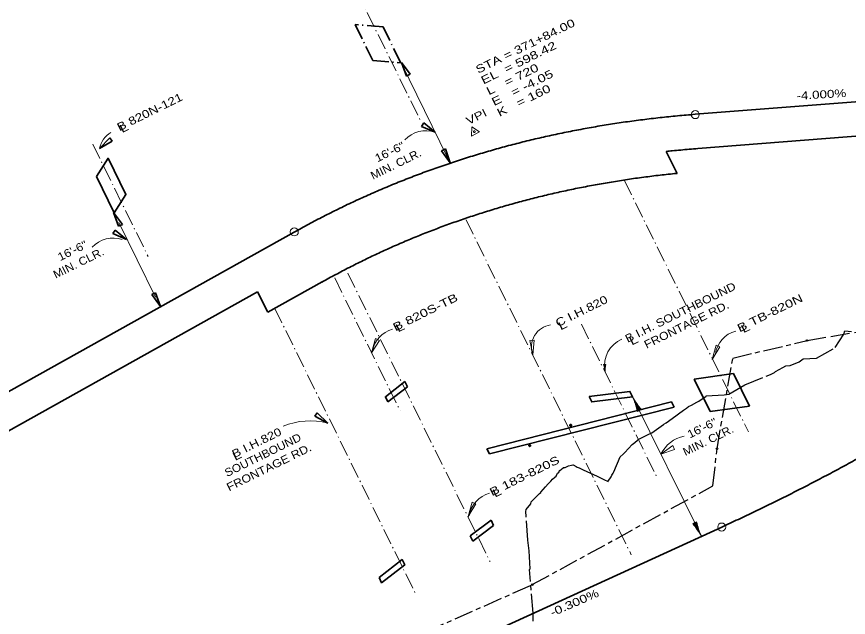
# Model space of a CAD drawing. Extents: x 2356431 to 2371438, y 6972864 to 6982525.
# Drawn here: x 2364327 to 2365783, y 6976877 to 6977927 of the extents above; entities that cross this region are included whole.
import ezdxf
from ezdxf.enums import TextEntityAlignment as Align

# ---------------------------------------------------------------- set-up
doc = ezdxf.new("R2010")
doc.units = 0
doc.header["$LTSCALE"] = 5.6
doc.header["$PDMODE"] = 32
doc.header["$PDSIZE"] = 2.8
for name, pattern in [('DASH_DOUBLE_DOT', [9.2, 5, -1.2, 0.3, -1.2, 0.3, -1.2]), ('DOT_DASHED', [7.7, 5, -1.2, 0.3, -1.2]), ('LONG_DASH_SHORT_DASH', [9.9, 6, -1.2, 1.5, -1.2]), ('LONG_DASHED', [7.5, 6, -1.5])]:
    doc.linetypes.add(name, pattern=pattern)
for name, color, linetype, lineweight in [('1', 7, 'Continuous', 25), ('2', 7, 'Continuous', 35), ('4', 7, 'LONG_DASHED', 35), ('44', 7, 'Continuous', 13), ('52', 7, 'Continuous', 25), ('53', 7, 'Continuous', 13), ('55', 7, 'Continuous', 13), ('61', 7, 'Continuous', 13)]:
    doc.layers.add(name, color=color, linetype=linetype, lineweight=lineweight)

msp = doc.modelspace()

# ---------------------------------------------------------------- linework, layer by layer
at = {"layer": '1', "lineweight": 13}
for p, q in [((2365000.648, 6977844.926), (2365081.574, 6977680.954)), ((2364506.093, 6977566.991), (2364570.478, 6977436.533)), ((2365525.628, 6977018.423), (2365405.321, 6977262.187)), ((2365417.237, 6977238.348), (2365406.115, 6977260.882)), ((2365416.34, 6977237.905), (2365408.719, 6977253.347)), ((2365415.443, 6977237.464), (2365411.139, 6977246.182)), ((2365418.134, 6977238.79), (2365411.627, 6977251.972)), ((2365414.546, 6977237.02), (2365412.438, 6977241.292)), ((2365419.03, 6977239.233), (2365415.245, 6977246.903)), ((2365419.927, 6977239.677), (2365418.525, 6977242.519)), ((2365420.555, 6977239.987), (2365413.686, 6977236.595)), ((2365517.272, 6977044.018), (2365510.402, 6977040.629)), ((2365511.262, 6977041.053), (2365513.371, 6977036.781)), ((2365512.16, 6977041.495), (2365516.462, 6977032.776)), ((2365513.056, 6977041.939), (2365520.677, 6977026.497)), ((2365513.953, 6977042.381), (2365525.074, 6977019.846)), ((2365514.85, 6977042.824), (2365521.355, 6977029.641)), ((2365515.746, 6977043.266), (2365519.532, 6977035.596)), ((2365516.644, 6977043.708), (2365518.047, 6977040.866))]:
    msp.add_line(p, q, dxfattribs=at)
at = {"layer": '1', "linetype": 'LONG_DASHED'}
msp.add_line((2365710.484, 6977360.825), (2365813.438, 6977378.181), dxfattribs=at)
at = {"layer": '1', "linetype": 'LONG_DASH_SHORT_DASH'}
msp.add_line((2365580.625, 6977330.192), (2365710.484, 6977360.825), dxfattribs=at)
at = {"layer": '1', "lineweight": 35}
for p, q in [((2365581.757, 6977302.943), (2365512.819, 6977293.496)), ((2365581.757, 6977302.943), (2365609.754, 6977246.215)), ((2365011.429, 6977279.861), (2365006.852, 6977288.965)), ((2365512.819, 6977293.496), (2365540.817, 6977236.768)), ((2365011.429, 6977279.861), (2364977.202, 6977253.322)), ((2365150.172, 6977171.65), (2365473.244, 6977253.649)), ((2365154.697, 6977162.482), (2365477.769, 6977244.48)), ((2365540.817, 6977236.768), (2365609.754, 6977246.215)), ((2365121.151, 6977019.338), (2365157.582, 6977046.748)), ((2365162.086, 6977037.624), (2365125.655, 6977010.212))]:
    msp.add_line(p, q, dxfattribs=at)
at = {"layer": '1', "linetype": 'DOT_DASHED', "lineweight": 35}
for p, q in [((2365473.244, 6977253.649), (2365477.769, 6977244.48)), ((2365150.172, 6977171.65), (2365154.697, 6977162.482)), ((2365162.086, 6977037.624), (2365157.582, 6977046.748)), ((2365125.655, 6977010.212), (2365121.151, 6977019.338))]:
    msp.add_line(p, q, dxfattribs=at)
msp.add_lwpolyline([(2364919.576, 6977913.6), (2364950.571, 6977850.73), (2364999.475, 6977846.547), (2364968.548, 6977909.412)], close=True, dxfattribs=at)
at = {"layer": '1', "lineweight": 35}
for points in [[(2364467.401, 6977647.828), (2364487.385, 6977679.495), (2364518.522, 6977616.406), (2364498.108, 6977584.057)], [(2365329.052, 6977263.07), (2365333.744, 6977253.562), (2365405.321, 6977262.187), (2365400.629, 6977271.695)], [(2364961.741, 6976946.434), (2364966.132, 6976937.183), (2365006.446, 6976968.48), (2365001.96, 6976977.658)]]:
    msp.add_lwpolyline(points, close=True, dxfattribs=at)
at = {"layer": '1', "linetype": 'LONG_DASH_SHORT_DASH'}
for points in [[(2365696.943, 6977323.601), (2365703.747, 6977328.612), (2365727.251, 6977329.851), (2365759.535, 6977348.332), (2365774.896, 6977372.139), (2365776.602, 6977378.009), (2365788.527, 6977376.384)], [(2365545.923, 6977106.752), (2365552.968, 6977171.566), (2365580.625, 6977330.192)], [(2365231.489, 6976870.234), (2365231.213, 6976884.244), (2365224.719, 6976960.192), (2365225.915, 6976961.587), (2365224.366, 6976993.249), (2365222.187, 6977011.741), (2365218.96, 6977053.431), (2365218.152, 6977061.273), (2365218.287, 6977061.925), (2365218.398, 6977062.063), (2365219.066, 6977065.585), (2365226.967, 6977075.214), (2365227.979, 6977078.764), (2365234.24, 6977085.146), (2365241.389, 6977092.19), (2365242.571, 6977093.319), (2365244.909, 6977095.133), (2365244.9, 6977095.738), (2365252.783, 6977104.706), (2365257.27, 6977110.433), (2365261.913, 6977115.144), (2365264.991, 6977118.395), (2365269.221, 6977121.978), (2365271.718, 6977123.81), (2365273.849, 6977128.888), (2365276.627, 6977130.399), (2365276.375, 6977131.224), (2365278.129, 6977133.77), (2365283.55, 6977138.013), (2365284.587, 6977138.827), (2365287.091, 6977138.567), (2365292.866, 6977141.552), (2365298.467, 6977142.926), (2365300.844, 6977143.241), (2365300.976, 6977143.333), (2365306.357, 6977140.526), (2365307.969, 6977139.499), (2365311.796, 6977138.278), (2365318.665, 6977134.921), (2365343.499, 6977123.765), (2365355.118, 6977117.748), (2365362.208, 6977114.101), (2365362.487, 6977114.484), (2365362.567, 6977114.638), (2365367.769, 6977122.484), (2365369.117, 6977125.399), (2365371.155, 6977128.7), (2365372.591, 6977131.009), (2365383.678, 6977157.619), (2365388.875, 6977161.955), (2365391.856, 6977164.839), (2365404.373, 6977178.738), (2365409.097, 6977182.337), (2365413.963, 6977186.598), (2365414.508, 6977187.142), (2365415.668, 6977187.796), (2365416.15, 6977188.312), (2365432.613, 6977196.484), (2365438.629, 6977199.66), (2365459.612, 6977214.011), (2365459.649, 6977214.049), (2365459.852, 6977214.203), (2365460.088, 6977214.357), (2365463.719, 6977217.099), (2365474.732, 6977224.315), (2365494.511, 6977238.756), (2365499.494, 6977242.419), (2365502.225, 6977244.995), (2365503.001, 6977245.592), (2365508.445, 6977247.6), (2365517.367, 6977252.816), (2365521.103, 6977254.759), (2365533.841, 6977263.766), (2365534.276, 6977264.081), (2365565.437, 6977265.74), (2365573.454, 6977266.921), (2365601.618, 6977283.534), (2365646.577, 6977301.307), (2365653.655, 6977304.84), (2365655.413, 6977306.698), (2365668.032, 6977313.69), (2365673.224, 6977316.275), (2365680.834, 6977316.833), (2365696.943, 6977323.601)], [(2364790.419, 6976739.461), (2365229.723, 6976933.969), (2365545.923, 6977106.752)]]:
    msp.add_lwpolyline(points, dxfattribs=at)
at = {"layer": '1', "lineweight": 35}
msp.add_lwpolyline([(2364977.202, 6977253.322), (2364972.624, 6977262.427), (2365006.852, 6977288.965)], dxfattribs=at)
at = {"layer": '1', "lineweight": 13}
for centre, radius, start, end in [((2364513.594, 6977688.517), 41.969, 120.5749, 168.88863), ((2365043.299, 6977678.665), 49.058, 70.65037, 138.00729), ((2364495.951, 6977490.94), 49.058, 70.65037, 138.00729), ((2365267.375, 6977349.263), 39.159, 98.08545, 200.23887), ((2364998.289, 6977333.312), 49.143, 105.45269, 171.47396), ((2365598.754, 6977330.069), 49.143, 105.45269, 171.47396), ((2365405.905, 6977317.453), 49.6, 113.0172, 190.70759), ((2365272.809, 6977204.748), 144.431, 12.73827, 23.42432), ((2365531.523, 6977332.432), 144.431, 209.11143, 219.79748), ((2364841.191, 6977096.522), 123.831, 75.743, 112.40222), ((2365506.777, 6977136.854), 57.828, 100.98701, 154.21632), ((2365168.069, 6977046.691), 49.143, 105.45269, 171.47396), ((2365399.433, 6976948.181), 144.431, 29.11144, 39.79749), ((2365658.147, 6977075.865), 144.431, 192.73827, 203.42432)]:
    msp.add_arc(centre, radius, start, end, dxfattribs=at)
at = {"layer": '2'}
msp.add_line((2364945.745, 6976753.555), (2365561.252, 6977034.695), dxfattribs=at)
msp.add_spline([(2365561.252, 6977034.695), (2365575.796, 6977041.379), (2365590.308, 6977048.127), (2365604.788, 6977054.941), (2365619.235, 6977061.819), (2365633.651, 6977068.763), (2365648.034, 6977075.771), (2365662.386, 6977082.845), (2365676.705, 6977089.985), (2365690.992, 6977097.189), (2365705.247, 6977104.458), (2365719.47, 6977111.792), (2365733.66, 6977119.192), (2365747.819, 6977126.656), (2365761.945, 6977134.186), (2365776.039, 6977141.781), (2365790.101, 6977149.44), (2365804.131, 6977157.166), (2365818.129, 6977164.956), (2365832.095, 6977172.812), (2365846.028, 6977180.732), (2365859.93, 6977188.717), (2365873.799, 6977196.768), (2365887.636, 6977204.883), (2365901.441, 6977213.065), (2365915.214, 6977221.311), (2365928.954, 6977229.622), (2365942.663, 6977237.998), (2365944.224, 6977238.957)], degree=3, dxfattribs=at)
at = {"layer": '4'}
for p in [(2365296.922, 6977212.479), (2365225.179, 6977177.071)]:
    msp.add_point(p, dxfattribs=at)
at = {"layer": '44', "linetype": 'DOT_DASHED'}
for p, q in [((2364902.524, 6978011.936), (2365035.302, 6977742.903)), ((2364460.541, 6977704.253), (2364557.611, 6977507.57)), ((2365391.104, 6977640.512), (2365607.921, 6977201.195)), ((2365113.876, 6977571.911), (2365403.022, 6976986.041)), ((2364906.988, 6977478.376), (2365155.757, 6976974.317)), ((2364883.932, 6977470.142), (2364998.439, 6977238.127)), ((2364779.185, 6977416.983), (2365026.664, 6976915.539)), ((2365315.906, 6977389.129), (2365448.682, 6977120.097))]:
    msp.add_line(p, q, dxfattribs=at)
at = {"layer": '52', "linetype": 'LONG_DASH_SHORT_DASH', "lineweight": 13}
for p, q in [((2365124.111, 6977734.339), (2365123.13, 6977718.212)), ((2365123.13, 6977718.212), (2365137.59, 6977725.431)), ((2365124.111, 6977734.339), (2365137.59, 6977725.431))]:
    msp.add_line(p, q, dxfattribs=at)
at = {"layer": '52', "lineweight": 13}
for centre in [(2365514.983, 6977755.734), (2364813.317, 6977550.749)]:
    msp.add_circle(centre, 7, dxfattribs=at)
at = {"layer": '52', "linetype": 'LONG_DASH_SHORT_DASH', "lineweight": 13}
msp.add_circle((2365128.269, 6977725.986), 1.5, dxfattribs=at)
at = {"layer": '52'}
for p in [(2365710.484, 6977360.825), (2365552.968, 6977171.566), (2365229.723, 6976933.969)]:
    msp.add_point(p, dxfattribs=at)
at = {"layer": '53', "lineweight": 35}
for p, q in [((2365514.614, 6977756.311), (2366355.88, 6977822.203)), ((2365519.299, 6977696.494), (2366384.586, 6977764.268)), ((2365464.089, 6977691.365), (2365482.971, 6977653.107)), ((2362763.128, 6976407.438), (2364813.246, 6977550.503)), ((2364766.838, 6977410.135), (2364861.944, 6977463.162)), ((2362792.347, 6976355.033), (2364749.113, 6977446.049)), ((2364749.113, 6977446.049), (2364766.838, 6977410.135))]:
    msp.add_line(p, q, dxfattribs=at)
at = {"layer": '53', "linetype": 'DASH_DOUBLE_DOT', "lineweight": 35}
for points in [[(2365009.623, 6977823.052), (2365000.902, 6977847.113), (2365016.306, 6977826.411)], [(2365039.972, 6977741.424), (2365059.553, 6977724.953), (2365035.859, 6977735.178)], [(2364494.727, 6977709.123), (2364472.41, 6977696.605), (2364490.331, 6977715.173)], [(2365077.784, 6977695.824), (2365086.084, 6977671.621), (2365071.041, 6977692.589)], [(2364505.819, 6977560.515), (2364497.098, 6977584.576), (2364512.502, 6977563.874)], [(2364500.082, 6977554.041), (2364519.663, 6977537.57), (2364495.969, 6977547.795)], [(2364570.611, 6977444.266), (2364578.911, 6977420.063), (2364563.868, 6977441.031)], [(2364853.545, 6977234.584), (2364871.686, 6977216.539), (2364848.927, 6977228.702)]]:
    msp.add_lwpolyline(points, close=True, dxfattribs=at)
at = {"layer": '53'}
msp.add_lwpolyline([(2365478.839, 6977170.513), (2365454.706, 6977162.008), (2365475.545, 6977177.228)], close=True, dxfattribs=at)
at = {"layer": '53', "lineweight": 35}
for points in [[(2364813.246, 6977550.503), (2364825.867, 6977557.466), (2364838.546, 6977564.313), (2364851.282, 6977571.044), (2364864.076, 6977577.658), (2364876.927, 6977584.157), (2364889.836, 6977590.539), (2364902.801, 6977596.805), (2364915.824, 6977602.955), (2364928.905, 6977608.988), (2364942.043, 6977614.905), (2364955.239, 6977620.706), (2364968.491, 6977626.392), (2364981.801, 6977631.96), (2364995.169, 6977637.412), (2365008.594, 6977642.749), (2365022.076, 6977647.969), (2365035.616, 6977653.073), (2365049.213, 6977658.061), (2365062.867, 6977662.932), (2365076.579, 6977667.687), (2365090.348, 6977672.326), (2365104.175, 6977676.85), (2365118.058, 6977681.256), (2365132, 6977685.546), (2365145.999, 6977689.721), (2365160.054, 6977693.778), (2365174.167, 6977697.721), (2365188.338, 6977701.546), (2365202.566, 6977705.255), (2365216.852, 6977708.849), (2365231.195, 6977712.326), (2365245.595, 6977715.687), (2365260.053, 6977718.931), (2365274.568, 6977722.059), (2365289.141, 6977725.072), (2365303.771, 6977727.968), (2365318.458, 6977730.748), (2365333.202, 6977733.411), (2365348.005, 6977735.958), (2365362.864, 6977738.39), (2365377.781, 6977740.705), (2365392.755, 6977742.904), (2365407.786, 6977744.986), (2365422.875, 6977746.952), (2365438.022, 6977748.803), (2365453.225, 6977750.537), (2365468.486, 6977752.155), (2365483.805, 6977753.656), (2365499.18, 6977755.042), (2365514.614, 6977756.311)], [(2365464.089, 6977691.365), (2365474.574, 6977692.464), (2365489.425, 6977693.919), (2365504.331, 6977695.263), (2365519.529, 6977696.512)], [(2364861.55, 6977462.943), (2364873.78, 6977469.69), (2364885.668, 6977476.111), (2364897.607, 6977482.42), (2364909.602, 6977488.621), (2364921.651, 6977494.714), (2364933.753, 6977500.697), (2364945.909, 6977506.572), (2364958.117, 6977512.337), (2364970.381, 6977517.994), (2364982.7, 6977523.542), (2364995.074, 6977528.982), (2365007.503, 6977534.314), (2365019.983, 6977539.535), (2365032.522, 6977544.65), (2365045.117, 6977549.656), (2365057.767, 6977554.554), (2365070.473, 6977559.344), (2365083.232, 6977564.024), (2365096.051, 6977568.597), (2365108.927, 6977573.063), (2365121.859, 6977577.42), (2365134.848, 6977581.669), (2365147.891, 6977585.809), (2365160.995, 6977589.841), (2365174.155, 6977593.766), (2365187.373, 6977597.581), (2365200.651, 6977601.29), (2365213.983, 6977604.889), (2365227.377, 6977608.381), (2365240.829, 6977611.765), (2365254.34, 6977615.04), (2365267.909, 6977618.207), (2365281.535, 6977621.265), (2365295.224, 6977624.215), (2365308.971, 6977627.057), (2365322.779, 6977629.79), (2365336.646, 6977632.415), (2365350.57, 6977634.93), (2365364.558, 6977637.337), (2365378.605, 6977639.636), (2365392.714, 6977641.825), (2365406.882, 6977643.906), (2365421.108, 6977645.877), (2365435.399, 6977647.739), (2365449.753, 6977649.492), (2365464.162, 6977651.137), (2365478.633, 6977652.67), (2365482.971, 6977653.107)]]:
    msp.add_spline(points, degree=3, dxfattribs=at)
at = {"layer": '55'}
for p, q in [((2365354.355, 6977318.718), (2365358.175, 6977319.014)), ((2365354.703, 6977318.823), (2365354.825, 6977317.244)), ((2365355.202, 6977318.863), (2365355.531, 6977314.599)), ((2365355.701, 6977318.901), (2365356.265, 6977311.573)), ((2365356.199, 6977318.94), (2365357.166, 6977306.411)), ((2365356.698, 6977318.978), (2365357.36, 6977310.394)), ((2365357.197, 6977319.017), (2365357.57, 6977314.169)), ((2365357.695, 6977319.055), (2365357.878, 6977316.68))]:
    msp.add_line(p, q, dxfattribs=at)
for centre, start, end in [((2365285.651, 6977296.472), 7.25574, 17.94179), ((2365429.477, 6977307.569), 170.88258, 181.56863)]:
    msp.add_arc(centre, 72.216, start, end, dxfattribs=at)
at = {"layer": '61'}
for points in [[(2364962.086, 6977360.967), (2364948.632, 6977339.202), (2364955.308, 6977364.129)], [(2365232.816, 6977361.211), (2365230.634, 6977335.717), (2365225.341, 6977360.974)], [(2365557.997, 6977349.653), (2365544.543, 6977327.888), (2365551.219, 6977352.815)], [(2365131.116, 6977075.115), (2365117.662, 6977053.35), (2365124.338, 6977078.277)]]:
    msp.add_lwpolyline(points, close=True, dxfattribs=at)
msp.add_circle((2365561.252, 6977034.695), 7, dxfattribs=at)

# ---------------------------------------------------------------- texts
at = {"layer": '1'}
for s, width, p in [('B 820N-121', 1.25, (2364563.37, 6977754.152)), ('L', 1.4, (2364518.197, 6977726.698)), ('16\'-6"', 1.15, (2364983.302, 6977684.389)), ('MIN. CLR.', 1.1, (2364994.073, 6977662.941)), ('16\'-6"', 1.15, (2364427.987, 6977511.585)), ('MIN. CLR.', 1.1, (2364438.758, 6977490.137)), ('B I.H. SOUTHBOUND', 1.15, (2365492.063, 6977403.784)), ('B 820S-TB', 1.35, (2365045.558, 6977403.972)), ('C I.H.820', 1.25, (2365318.961, 6977405.991)), ('B TB-820N', 1.35, (2365648.586, 6977402.577)), ('FRONTAGE RD.', 1.15, (2365502.633, 6977382.235)), ('L', 1.4, (2365001.373, 6977378.024)), ('L', 1.4, (2365285.785, 6977381.619)), ('L', 1.4, (2365605.659, 6977376.561)), ('L', 1.4, (2365410.308, 6977355.075)), ('16\'-6"', 1.15, (2365529.843, 6977201.508)), ('SOUTHBOUND', 1.1, (2364761.327, 6977154.403)), ('B I.H.820', 1.2, (2364750.506, 6977175.827)), ('MIN. CLR.', 1.1, (2365540.614, 6977180.06)), ('FRONTAGE RD.', 1.15, (2364772.046, 6977132.928)), ('L', 1.4, (2364716.108, 6977153.441)), ('B 183-820S', 1.35, (2365219.104, 6977117.833)), ('L', 1.4, (2365170.951, 6977089.173))]:
    msp.add_text(s, height=14, rotation=26.268, dxfattribs=dict(at, width=width)).set_placement(p, align=Align.CENTER)
at = {"layer": '2'}
for s, rotation, width, p in [('-4.000%', 3.337, 1.25, (2365692.499, 6977781.617)), ('-0.300%', 23.56, 1.3, (2365264.68, 6976877.736))]:
    msp.add_text(s, height=14, rotation=rotation, dxfattribs=dict(at, width=width)).set_placement(p)
at = {"layer": '52'}
for s, width, p in [('STA = 371+84.00', 1.3, (2365134.982, 6977827.137)), ('EL  = 598.42', 1.35, (2365144.275, 6977808.306)), ('L   = 720', 1.35, (2365153.569, 6977789.475)), ('E   = -4.05', 1.35, (2365162.863, 6977770.644)), ('K   = 160', 1.35, (2365172.157, 6977751.813))]:
    msp.add_text(s, height=14, rotation=26.268, dxfattribs=dict(at, width=width)).set_placement(p)
at = {"layer": '52', "width": 1.25}
msp.add_text('VPI', height=14, rotation=26.531, dxfattribs=at).set_placement((2365134.967, 6977745.866), align=Align.CENTER)

doc.saveas('drawing.dxf')
